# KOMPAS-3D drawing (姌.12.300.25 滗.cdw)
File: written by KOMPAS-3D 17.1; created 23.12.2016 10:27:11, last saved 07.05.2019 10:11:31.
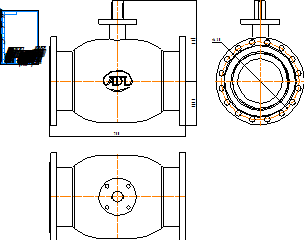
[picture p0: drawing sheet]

Sheet 1: A4, portrait

Title block, sheet 1: name: КШ.12.300.25 фф; material: Внимание! Данный продукт является объектом авторского права ООО «Торговый Дом АДЛ». / Запрещается изменение, копирование, распространение / (в том числе путем копирования на другие сайты и ресурсы в Интернете) / или любое иное использование информации и объектов без предварительного / согласия правообладателя (ООО «Торговый Дом АДЛ»).; sheets: 1; organisation: ООО "Торговый дом АДЛ"; sheet format: A4; stored path: C:\Users\tra\Desktop\2д чертежи\Шаровые краны БИВАЛ\КШ_Бивал_серия_11_12\KOMPAS_2D\КШ.12.300.25 фф.cdw

Views: Вид 1, Проекционный вид 2, Проекционный вид 3
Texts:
  Klimkovich
  ADL
Dimensions and other numbers on the sheet: 750; 441; 242,5; 430; 1:1; 1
